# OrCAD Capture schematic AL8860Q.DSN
size Custom; title: AL8860Q, 40V 1.5A Automotive Grade Buck LED DRIVER; rev: 1.2; note: DS41797 Rev. 2 - 2
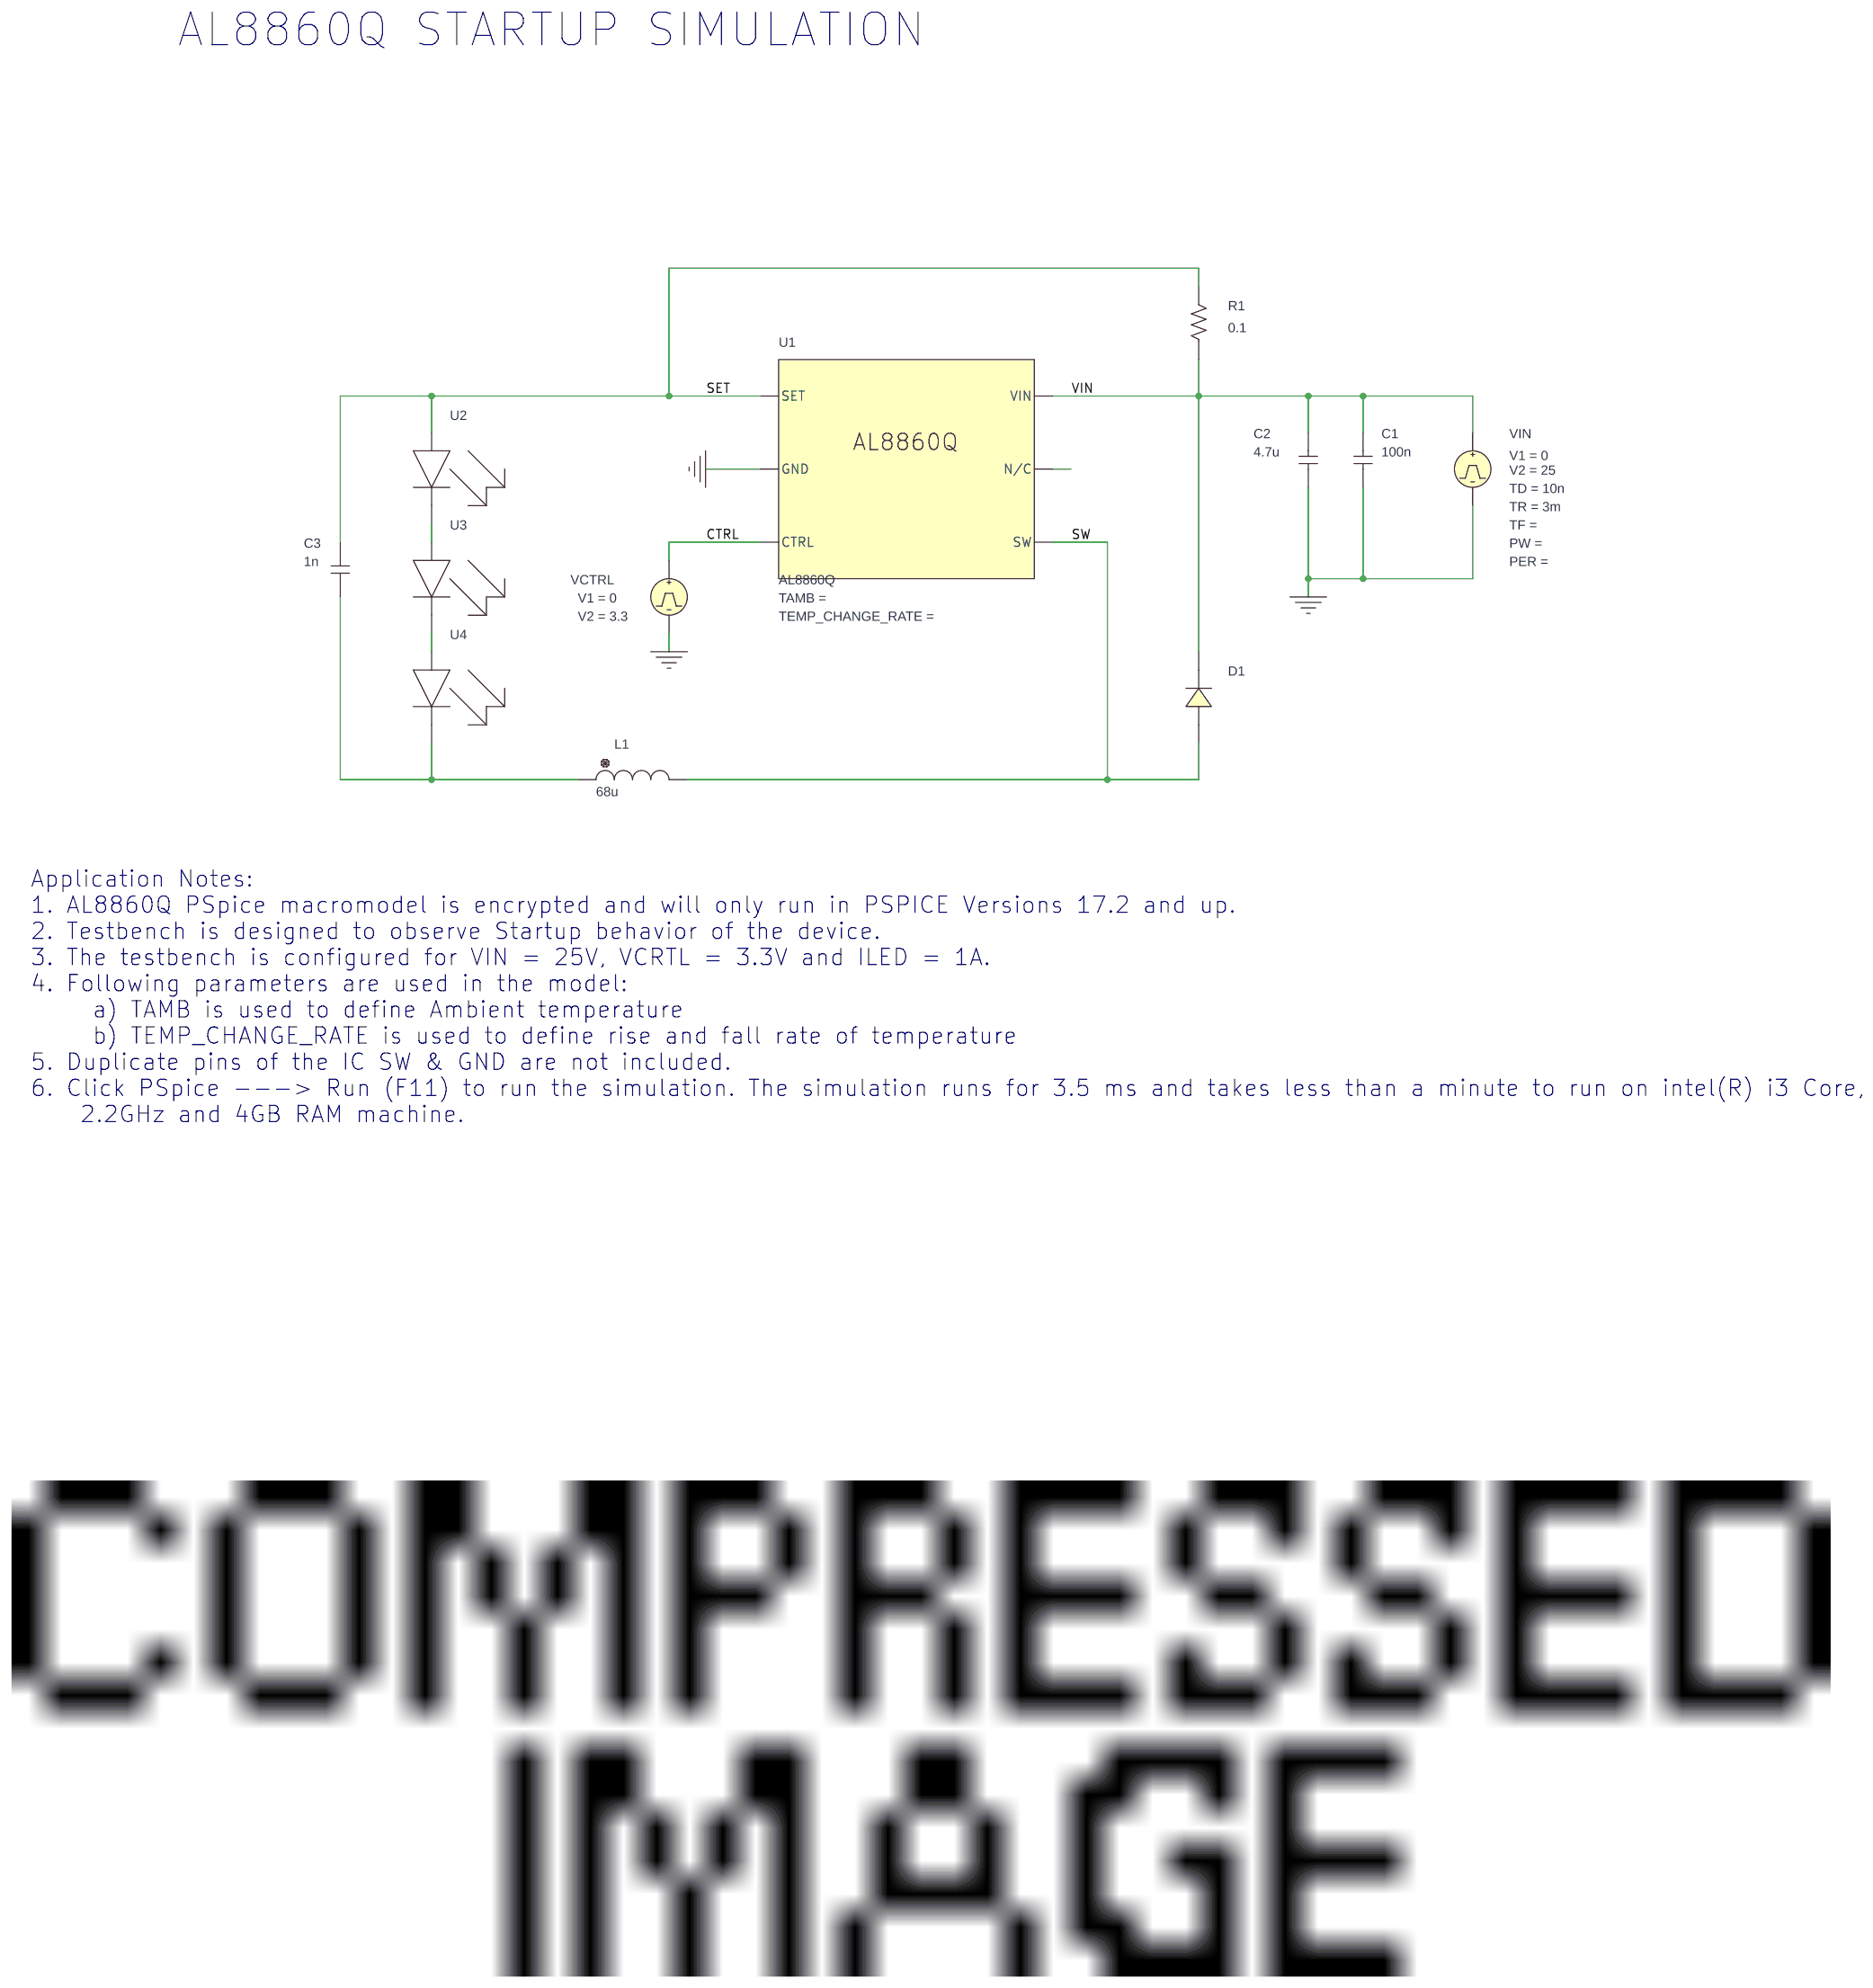
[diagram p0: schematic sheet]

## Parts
C1  100n  [RAD/CK05]
C2  4.7u  [RAD/CK05]
C3  1n  [RAD/CK05]
D1  B240A
L1  68u  [DISC/.350x.175/LS.200x.100/.034]
R1  0.1  [AX/RC05]
U1  AL8860Q
U2  _D2_mod
U3  _D2_mod
U4  _D2_mod
VCTRL  VPULSE
VIN  VPULSE

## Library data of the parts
C1-C3 = C
D1 = B240A
L1 = L: IC: 0
R1 = R
U1 = AL8860Q
U2-U4 = LEDR
VCTRL = VPULSE: V1: 0; V2: 3.3
VIN = VPULSE: TD: 10n; TR: 3m; V1: 0; V2: 25

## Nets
VIN: C1.2 C2.2 D1.1(C) R1.1 U1.VIN VIN.1(+)
0: C1.1 C2.1 U1.GND VCTRL.2(-) VIN.2(-)
CTRL: U1.CTRL VCTRL.1(+)
SET: C3.2 R1.2 U1.SET U2.1(A)
SW: D1.2(A) L1.2 U1.SW
N19056: U2.2(C) U3.1(A)
N19106: U3.2(C) U4.1(A)
N19208: C3.1 L1.1 U4.2(C)

Not connected (* = marked no-connect by the designer): U1 N/C

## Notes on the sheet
- AL8860Q STARTUP SIMULATION
- Application Notes:
  1. AL8860Q PSpice macromodel is encrypted and will only run in PSPICE Versions 17.2 and up.
  2. Testbench is designed to observe Startup behavior of the device.
  3. The testbench is configured for VIN = 25V, VCRTL = 3.3V and ILED = 1A.
  4. Following parameters are used in the model:
       a) TAMB is used to define Ambient temperature
       b) TEMP_CHANGE_RATE is used to define rise and fall rate of temperature
  5. Duplicate pins of the IC SW & GND are not included.
  6. Click PSpice ---> Run (F11) to run the simulation. The simulation runs for 3.5 ms and takes less than a minute to run on intel(R) i3 Core,
      2.2GHz and 4GB RAM machine.
